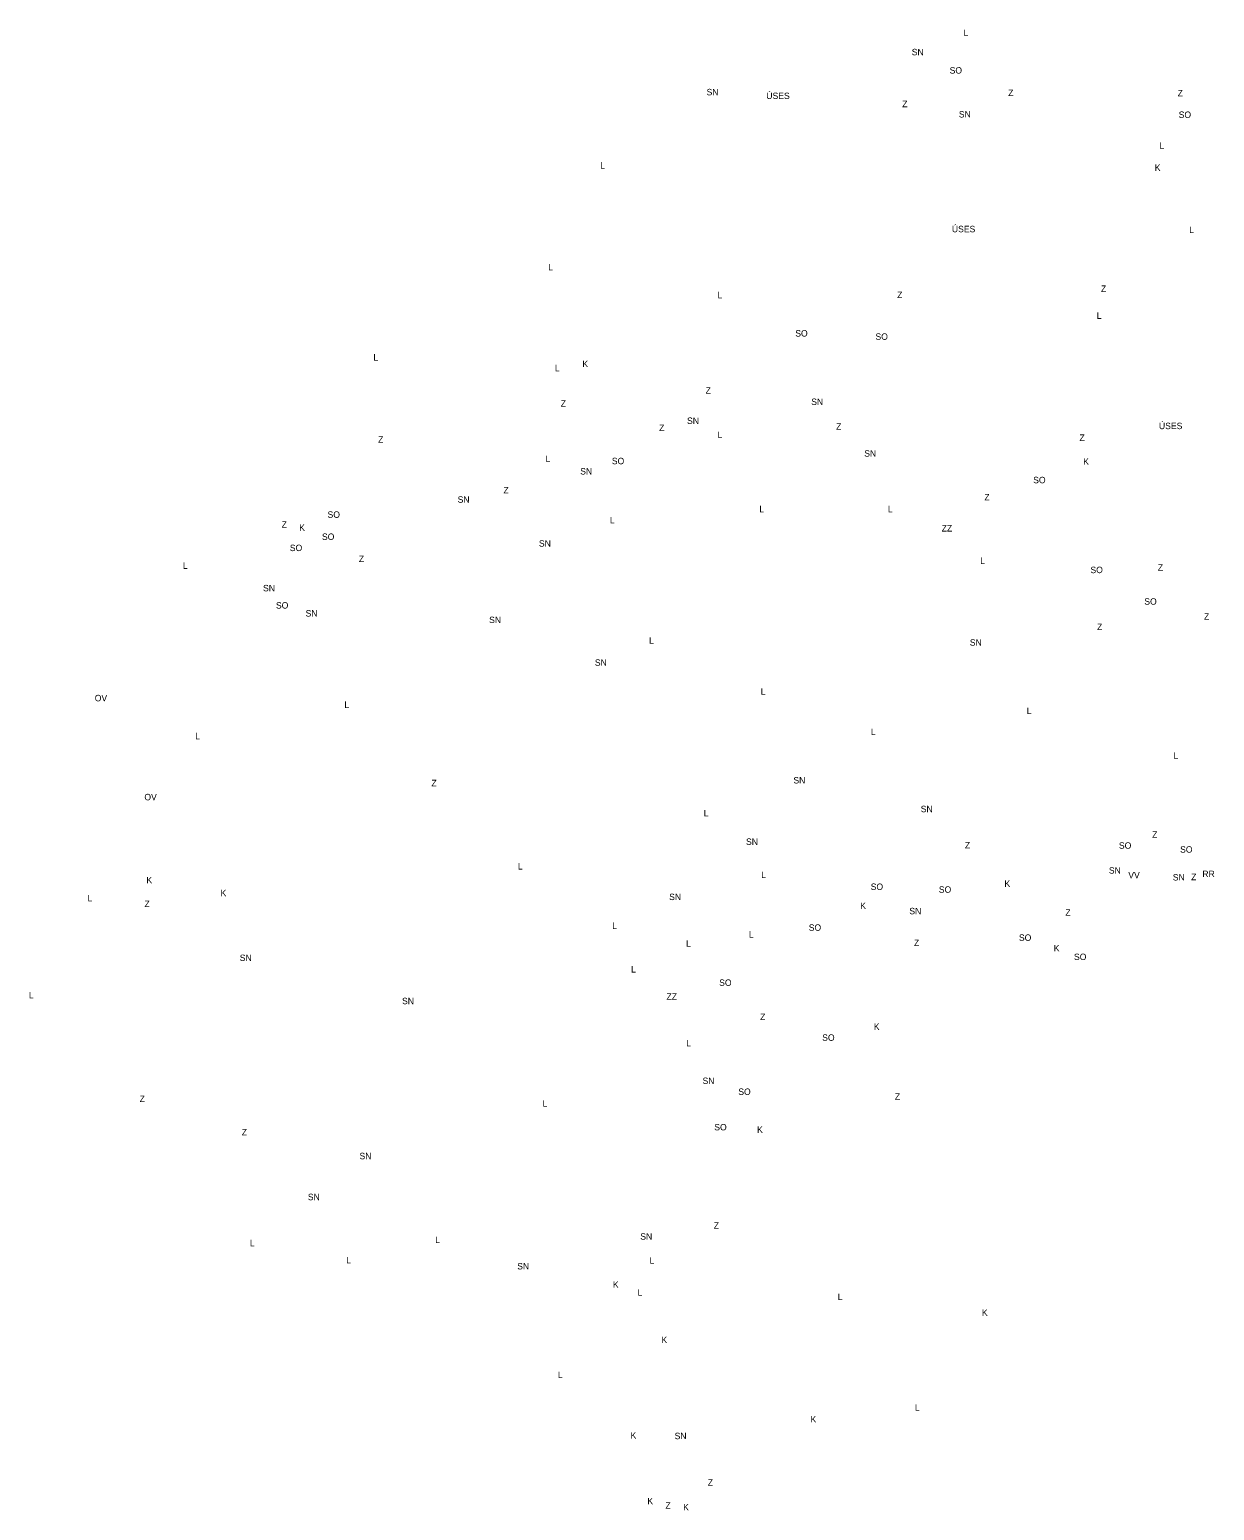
# Model space of a CAD drawing. Extents: x -445021 to -436233, y -1141846 to -1129798.
# Drawn here: x -445021 to -443178, y -1134464 to -1132160 of the extents above; entities that cross this region are included whole.
import ezdxf

# ---------------------------------------------------------------- set-up
doc = ezdxf.new("R2010")
doc.units = 0
doc.layers.add('Vrstva 4', color=7, linetype='Continuous')

msp = doc.modelspace()

# ---------------------------------------------------------------- texts
at = {"layer": 'Vrstva 4'}
for s, p in [('L', (-443568.4, -1132169.6)), ('SN', (-443649, -1132199.5)), ('SO', (-443590, -1132228)), ('SN', (-443968.2, -1132261.8)), ('ÚSES', (-443875.2, -1132267.6)), ('Z', (-443498.9, -1132263)), ('Z', (-443235.2, -1132263.5)), ('Z', (-443663.8, -1132280.3)), ('SN', (-443575.7, -1132296.3)), ('SO', (-443233.6, -1132297)), ('L', (-443263.4, -1132345.2)), ('L', (-444133.8, -1132375.8)), ('K', (-443270.8, -1132379.4)), ('ÚSES', (-443586.5, -1132474.9)), ('L', (-443217.3, -1132476.1)), ('L', (-444214.5, -1132534.2)), ('L', (-443951.2, -1132577.6)), ('Z', (-443671.7, -1132577.4)), ('Z', (-443354.5, -1132567.7)), ('L', (-443361.2, -1132609.7)), ('SO', (-443830.2, -1132637.2)), ('SO', (-443705.4, -1132642.3)), ('L', (-444486.6, -1132674.6)), ('L', (-444204.3, -1132691.2)), ('K', (-444161.4, -1132684.8)), ('Z', (-443969.6, -1132726)), ('Z', (-444195.1, -1132746.4)), ('SN', (-443805.4, -1132743.7)), ('SN', (-443998.6, -1132773.2)), ('Z', (-444041.9, -1132784.1)), ('L', (-443951.2, -1132795)), ('Z', (-443766.7, -1132782.3)), ('ÚSES', (-443264.3, -1132781.3)), ('Z', (-444479.2, -1132802.3)), ('Z', (-443387.9, -1132799.6)), ('L', (-444218.8, -1132832.4)), ('SO', (-444115.6, -1132835.9)), ('SN', (-443722.9, -1132824.1)), ('K', (-443382.1, -1132836.7)), ('SN', (-444164.8, -1132851.9)), ('SO', (-443460, -1132865.5)), ('Z', (-444284.2, -1132881.3)), ('SN', (-444355.5, -1132895.9)), ('L', (-443886.1, -1132910.6)), ('L', (-443686, -1132910.6)), ('Z', (-443536, -1132892.3)), ('Z', (-444629.4, -1132934.8)), ('SO', (-444557.9, -1132919.3)), ('L', (-444118.7, -1132927.9)), ('K', (-444602.1, -1132939.6)), ('SO', (-444566.6, -1132953.7)), ('ZZ', (-443602.4, -1132940.6)), ('SO', (-444616.6, -1132971.1)), ('SN', (-444229, -1132964.2)), ('L', (-444782.9, -1132998.7)), ('Z', (-444509.2, -1132988.2)), ('L', (-443542.4, -1132991)), ('Z', (-443266, -1133001.5)), ('SO', (-443370.9, -1133005.4)), ('SN', (-444658.3, -1133033.7)), ('SO', (-444638.2, -1133060.5)), ('SN', (-444592.1, -1133072.9)), ('SO', (-443287.1, -1133054.5)), ('SN', (-444306.5, -1133083.1)), ('Z', (-443360.7, -1133094.1)), ('Z', (-443194.2, -1133077.8)), ('L', (-444057.6, -1133115.3)), ('SN', (-443558.6, -1133118.3)), ('SN', (-444142, -1133149.6)), ('OV', (-444920.1, -1133204.8)), ('L', (-443884, -1133194.7)), ('L', (-444531.6, -1133215.1)), ('L', (-443470.1, -1133224.7)), ('L', (-443712.5, -1133257.3)), ('L', (-444763.8, -1133263.9)), ('L', (-443241.5, -1133294.5)), ('Z', (-444396.2, -1133337)), ('SN', (-443833.1, -1133332.7)), ('OV', (-444842.9, -1133358.9)), ('L', (-443972.6, -1133384.1)), ('SN', (-443635, -1133377.4)), ('Z', (-443274.9, -1133417.2)), ('SN', (-443906.8, -1133428.3)), ('Z', (-443566.3, -1133433.9)), ('SO', (-443326.6, -1133434.3)), ('SO', (-443231.4, -1133440.4)), ('K', (-444839.7, -1133488.1)), ('L', (-444261.8, -1133466.6)), ('L', (-443883, -1133479.8)), ('SN', (-443342.3, -1133473)), ('VV', (-443312, -1133480.4)), ('SN', (-443242.8, -1133483.7)), ('Z', (-443214.2, -1133483.2)), ('RR', (-443196.8, -1133478.5)), ('K', (-444724.4, -1133508.2)), ('SO', (-443712.8, -1133498.4)), ('SO', (-443606.8, -1133502.8)), ('K', (-443504.7, -1133493.6)), ('L', (-444931.4, -1133516.1)), ('Z', (-444842.8, -1133525.2)), ('SN', (-444026.4, -1133514.2)), ('K', (-443729.1, -1133528)), ('SN', (-443652.7, -1133536.3)), ('Z', (-443410, -1133538.6)), ('L', (-444114.9, -1133559)), ('L', (-443902.4, -1133572.5)), ('SO', (-443809.2, -1133562)), ('SO', (-443482.2, -1133577.6)), ('L', (-444000.1, -1133586.7)), ('Z', (-443645.5, -1133585.7)), ('K', (-443428, -1133594)), ('SN', (-444694.5, -1133609)), ('SO', (-443396.5, -1133607.5)), ('L', (-444085.6, -1133626.9)), ('SO', (-443948.6, -1133647.7)), ('L', (-445022.6, -1133667.3)), ('ZZ', (-444030.5, -1133669.2)), ('SN', (-444442, -1133676.2)), ('Z', (-443884.8, -1133700.8)), ('K', (-443708, -1133716.2)), ('SO', (-443788.3, -1133733.2)), ('L', (-443999.7, -1133742)), ('SN', (-443974.5, -1133800.4)), ('Z', (-444850.2, -1133828.4)), ('SO', (-443918.8, -1133817.4)), ('Z', (-443675.2, -1133824.9)), ('L', (-444223.5, -1133835.6)), ('SO', (-443956.2, -1133872.6)), ('K', (-443889.6, -1133876.4)), ('Z', (-444691.4, -1133880.4)), ('SN', (-444508.2, -1133917.5)), ('SN', (-444588.6, -1133981.2)), ('Z', (-443957, -1134025.6)), ('L', (-444678.7, -1134052.9)), ('L', (-444390.5, -1134047.8)), ('SN', (-444071.3, -1134042.7)), ('L', (-444529, -1134079.4)), ('L', (-444056.8, -1134080.1)), ('SN', (-444262.8, -1134089)), ('K', (-444113.9, -1134117.5)), ('L', (-444075.7, -1134130)), ('L', (-443764.1, -1134136.6)), ('K', (-443539.8, -1134161.2)), ('K', (-444038.3, -1134203.6)), ('L', (-444199.6, -1134258.1)), ('L', (-443643.9, -1134308.7)), ('K', (-443806.4, -1134327.1)), ('K', (-444086.4, -1134352.3)), ('SN', (-444017.9, -1134353.1)), ('Z', (-443966.4, -1134425.6)), ('K', (-444060.3, -1134454.5)), ('Z', (-444032.1, -1134461.2)), ('K', (-444004.6, -1134463.9))]:
    msp.add_text(s, height=10, dxfattribs=at).set_placement(p)

doc.saveas('drawing.dxf')
